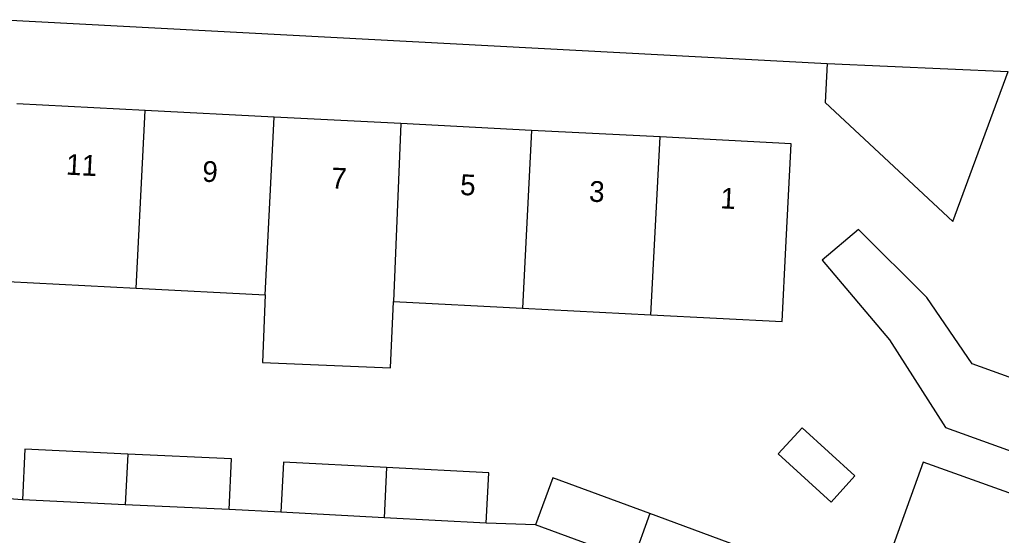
# Model space of a CAD drawing. Extents: x 161253 to 161848, y 384872 to 385383.
# Drawn here: x 161674.69 to 161721.92, y 385289.1 to 385313.93 of the extents above; entities that cross this region are included whole.
import ezdxf

# ---------------------------------------------------------------- set-up
doc = ezdxf.new("R2010")
doc.units = 0
for name, color, linetype in [('IMGEO_Pand', 7, 'Continuous'), ('IMGEO_Pand_nummerreeks', 7, 'Continuous'), ('IMGEO_Rijbaan_lokaal_open', 7, 'Continuous'), ('IMGEO_Voetpad_open', 7, 'Continuous')]:
    doc.layers.add(name, color=color, linetype=linetype)

msp = doc.modelspace()

# ---------------------------------------------------------------- linework, layer by layer
at = {"layer": 'IMGEO_Pand'}
for points in [[(161713.548, 385311.814), (161713.443, 385309.941), (161719.586, 385304.211), (161722.241, 385311.438)], [(161713.548, 385311.814), (161722.241, 385311.438)], [(161680.739, 385309.559), (161674.556, 385309.878)], [(161680.304, 385301.001), (161680.739, 385309.559)], [(161686.943, 385309.238), (161680.739, 385309.559)], [(161686.507, 385300.681), (161686.943, 385309.238)], [(161693.036, 385308.924), (161686.943, 385309.238)], [(161693.036, 385308.924), (161692.676, 385300.363)], [(161699.318, 385308.6), (161693.036, 385308.924)], [(161699.318, 385308.6), (161698.883, 385300.043)], [(161705.502, 385308.281), (161699.318, 385308.6)], [(161705.065, 385299.724), (161705.502, 385308.281)], [(161705.065, 385299.724), (161711.374, 385299.398), (161711.558, 385302.962), (161711.816, 385307.955), (161705.502, 385308.281)], [(161733.59, 385295.766), (161728.876, 385297.47), (161726.228, 385298.427), (161725.225, 385295.651), (161720.519, 385297.352), (161718.335, 385300.557), (161715.045, 385303.822), (161713.305, 385302.355), (161716.542, 385298.515), (161719.231, 385294.3), (161726.748, 385291.583), (161731.45, 385289.883)], [(161674.121, 385301.32), (161680.304, 385301.001)], [(161680.304, 385301.001), (161686.507, 385300.681)], [(161686.507, 385300.681), (161686.37, 385297.432), (161692.542, 385297.172), (161692.676, 385300.363)], [(161692.676, 385300.363), (161698.883, 385300.043)], [(161698.883, 385300.043), (161705.065, 385299.724)], [(161714.879, 385291.964), (161712.336, 385294.283), (161711.19, 385293.027), (161713.733, 385290.708), (161714.879, 385291.964)], [(161679.898, 385293.018), (161674.946, 385293.249), (161674.832, 385290.807)], [(161679.898, 385293.018), (161679.774, 385290.577)], [(161684.771, 385290.344), (161684.884, 385292.786), (161679.898, 385293.018)], [(161692.34, 385292.369), (161687.388, 385292.631), (161687.26, 385290.212)], [(161731.102, 385288.935), (161726.404, 385290.622), (161723.434, 385291.689), (161723.13, 385290.842), (161718.153, 385292.633), (161714.785, 385283.274), (161724.834, 385279.657), (161725.261, 385280.843), (161727.867, 385279.905)], [(161692.34, 385292.369), (161692.238, 385289.948)], [(161697.135, 385289.689), (161697.263, 385292.108), (161692.34, 385292.369)], [(161705.004, 385290.15), (161700.35, 385291.866), (161699.517, 385289.608)], [(161679.774, 385290.577), (161674.832, 385290.807)], [(161684.771, 385290.344), (161679.774, 385290.577)], [(161692.238, 385289.948), (161687.26, 385290.212)], [(161705.004, 385290.15), (161704.194, 385287.884)], [(161708.813, 385286.18), (161709.646, 385288.438), (161705.004, 385290.15)], [(161697.135, 385289.689), (161692.238, 385289.948)], [(161702.957, 385288.34), (161699.517, 385289.608)]]:
    msp.add_lwpolyline(points, dxfattribs=at)
at = {"layer": 'IMGEO_Rijbaan_lokaal_open'}
for points in [[(161674.832, 385290.807), (161672.397, 385290.986)], [(161687.26, 385290.212), (161684.771, 385290.344)], [(161699.517, 385289.608), (161697.135, 385289.689)]]:
    msp.add_lwpolyline(points, dxfattribs=at)
at = {"layer": 'IMGEO_Voetpad_open'}
msp.add_lwpolyline([(161655.951, 385313.166), (161655.95, 385313.238), (161655.959, 385313.378), (161655.979, 385313.517), (161656.012, 385313.654), (161656.057, 385313.787), (161656.114, 385313.916), (161656.182, 385314.039), (161656.261, 385314.156), (161656.35, 385314.265), (161656.449, 385314.366), (161656.556, 385314.457), (161656.67, 385314.539), (161656.792, 385314.61), (161656.919, 385314.669), (161657.051, 385314.718), (161657.187, 385314.754), (161657.326, 385314.778), (161657.466, 385314.789), (161657.607, 385314.788), (161713.548, 385311.814)], dxfattribs=at)

# ---------------------------------------------------------------- texts
at = {"layer": 'IMGEO_Pand_nummerreeks'}
for s, rotation, p in [('11', 357.0461, (161676.908, 385306.471)), ('9', 357.0461, (161683.458, 385306.134)), ('7', 357.0435, (161689.66, 385305.814)), ('5', 357.0461, (161695.864, 385305.494)), ('3', 357.0461, (161702.068, 385305.174)), ('1', 357.0461, (161708.385, 385304.848))]:
    msp.add_text(s, height=1, rotation=rotation, dxfattribs=at).set_placement(p)

doc.saveas('drawing.dxf')
